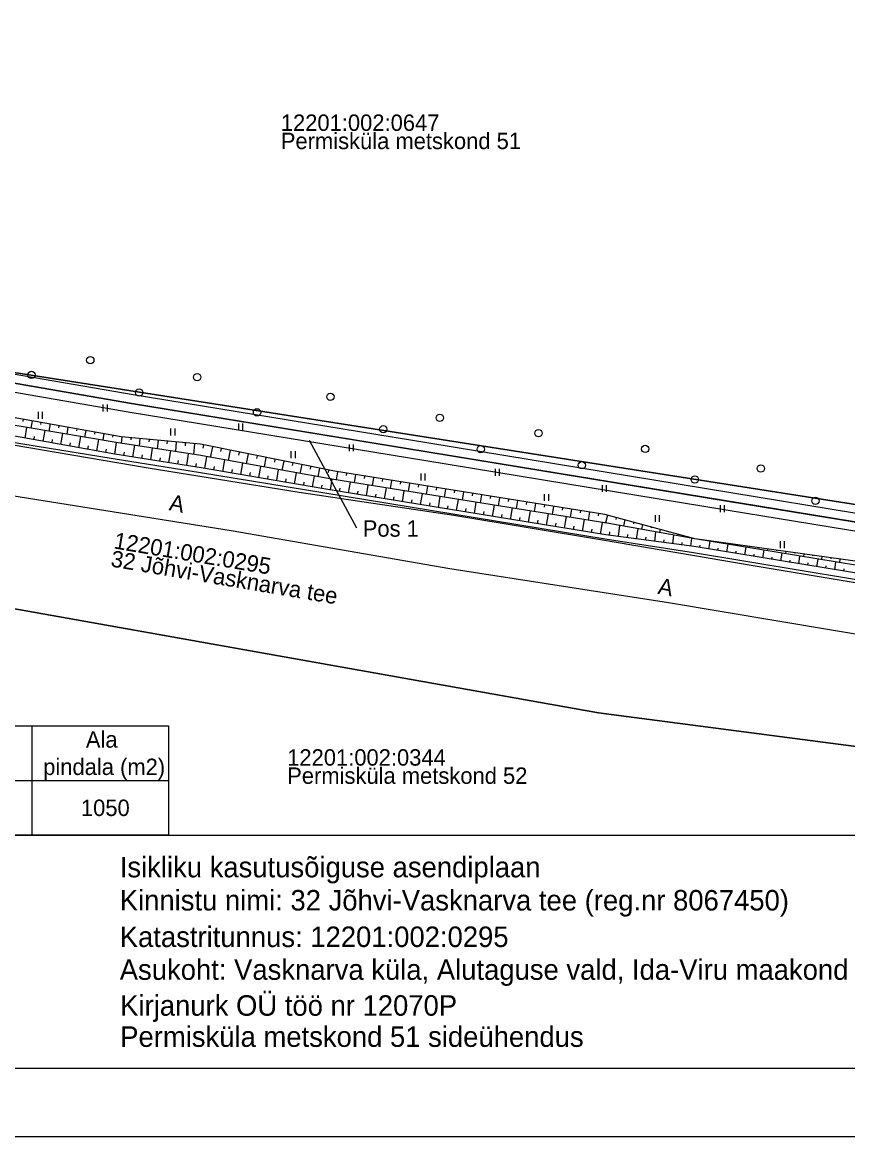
# Model space of a CAD drawing. Extents: x 712851 to 713448, y 6545714 to 6545930.
# Drawn here: x 713128.6 to 713219.1, y 6545742.3 to 6545864.7 of the extents above; entities that cross this region are included whole.
import ezdxf

# ---------------------------------------------------------------- set-up
doc = ezdxf.new("R2010")
doc.units = 0
for name, color, linetype in [('HALJASTUS', 7, 'Continuous'), ('KASUTUSALA', 7, 'Continuous'), ('PIIR', 7, 'Continuous'), ('PR_SIDE', 7, 'Continuous'), ('RELJEEF', 7, 'Continuous'), ('SITRASS', 7, 'Continuous'), ('TEE', 7, 'Continuous'), ('VORMISTUS_1', 7, 'Continuous')]:
    doc.layers.add(name, color=color, linetype=linetype)

msp = doc.modelspace()

# ---------------------------------------------------------------- linework, layer by layer
at = {"layer": 'HALJASTUS'}
for p, q in [((713130.29, 6545821.9), (713130.29, 6545821.14)), ((713130.74, 6545821.9), (713130.74, 6545821.14)), ((713137.41, 6545822.71), (713137.41, 6545821.95)), ((713137.87, 6545822.71), (713137.87, 6545821.95)), ((713152.26, 6545820.64), (713152.26, 6545819.88)), ((713152.71, 6545820.64), (713152.71, 6545819.88)), ((713144.83, 6545820.07), (713144.83, 6545819.31)), ((713145.29, 6545820.07), (713145.29, 6545819.31)), ((713164.41, 6545818.33), (713164.41, 6545817.57)), ((713164.86, 6545818.33), (713164.86, 6545817.57)), ((713158.03, 6545817.59), (713158.03, 6545816.82)), ((713158.49, 6545817.59), (713158.49, 6545816.82)), ((713180.42, 6545815.64), (713180.42, 6545814.88)), ((713180.87, 6545815.64), (713180.87, 6545814.88)), ((713172.28, 6545815.13), (713172.28, 6545814.37)), ((713172.73, 6545815.13), (713172.73, 6545814.37)), ((713192.18, 6545813.87), (713192.18, 6545813.11)), ((713192.63, 6545813.87), (713192.63, 6545813.11)), ((713185.83, 6545812.88), (713185.83, 6545812.12)), ((713186.29, 6545812.88), (713186.29, 6545812.12)), ((713205.11, 6545811.66), (713205.11, 6545810.89)), ((713205.56, 6545811.66), (713205.56, 6545810.89)), ((713197.98, 6545810.58), (713197.98, 6545809.82)), ((713198.44, 6545810.58), (713198.44, 6545809.82)), ((713211.69, 6545807.7), (713211.69, 6545806.94)), ((713212.15, 6545807.7), (713212.15, 6545806.94))]:
    msp.add_line(p, q, dxfattribs=at)
msp.add_lwpolyline([(713243.24, 6545806.02), (713233.71, 6545807.55), (713140.54, 6545822.83), (713103.81, 6545829.17), (713056.1, 6545836.44)], dxfattribs=at)
for centre in [(713136.02, 6545827.57), (713129.56, 6545825.95), (713147.75, 6545825.71), (713141.38, 6545824.03), (713162.36, 6545823.55), (713154.31, 6545821.85), (713174.36, 6545821.25), (713168.16, 6545819.99), (713185.19, 6545819.57), (713178.85, 6545817.8), (713196.9, 6545817.83), (713189.95, 6545816.04), (713209.58, 6545815.68), (713202.34, 6545814.48), (713215.57, 6545812.14)]:
    msp.add_circle(centre, 0.4, dxfattribs=at)
at = {"layer": 'KASUTUSALA'}
for points in [[(713019.19, 6545842.89), (713110.14, 6545828.97), (713117.77, 6545827.77), (713140.71, 6545823.82), (713173.15, 6545818.49), (713206.31, 6545813.05), (713233.87, 6545808.53)], [(713233.55, 6545806.56), (713205.99, 6545811.08), (713172.83, 6545816.52), (713140.38, 6545821.84), (713103.65, 6545828.18), (713077.53, 6545832.15), (713021.99, 6545840.54)]]:
    msp.add_lwpolyline(points, dxfattribs=at)
at = {"layer": 'PIIR'}
for points in [[(713056.1, 6545837.24), (713110.14, 6545828.97), (713225.78, 6545810.83), (713243.24, 6545807.88)], [(713243.24, 6545807.88), (713225.78, 6545810.83), (713110.14, 6545828.97), (713056.1, 6545837.24)], [(713056.1, 6545813.14), (713059.74, 6545812.48), (713083.79, 6545807.67), (713123.38, 6545801.06), (713158.31, 6545794.82), (713191.79, 6545788.86), (713223.65, 6545784.69), (713243.24, 6545781.2)], [(713243.24, 6545781.2), (713223.65, 6545784.69), (713191.79, 6545788.86), (713158.31, 6545794.82), (713123.38, 6545801.06), (713083.79, 6545807.67), (713059.74, 6545812.48), (713056.1, 6545813.14)]]:
    msp.add_lwpolyline(points, dxfattribs=at)
at = {"layer": 'PR_SIDE'}
msp.add_lwpolyline([(713056.1, 6545836.4), (713077.68, 6545833.14), (713103.81, 6545829.17), (713140.54, 6545822.83), (713172.99, 6545817.5), (713206.15, 6545812.06), (713233.71, 6545807.55), (713243.24, 6545806.02)], dxfattribs=at)
at = {"layer": 'RELJEEF'}
for p, q in [((713128.64, 6545821.09), (713128.6, 6545820.85)), ((713129.63, 6545820.92), (713129.49, 6545820.12)), ((713130.61, 6545820.74), (713130.57, 6545820.51)), ((713131.6, 6545820.57), (713131.46, 6545819.79)), ((713128.87, 6545819.03), (713129.07, 6545820.19)), ((713130.83, 6545818.68), (713131.05, 6545819.86)), ((713132.58, 6545820.39), (713132.54, 6545820.16)), ((713132.8, 6545818.32), (713133.02, 6545819.53)), ((713133.57, 6545820.21), (713133.43, 6545819.46)), ((713134.55, 6545820.04), (713134.51, 6545819.81)), ((713135.53, 6545819.86), (713135.4, 6545819.13)), ((713136.52, 6545819.69), (713136.48, 6545819.47)), ((713137.5, 6545819.51), (713137.38, 6545818.79)), ((713138.49, 6545819.33), (713138.45, 6545819.12)), ((713129.85, 6545818.85), (713129.91, 6545819.2)), ((713131.82, 6545818.5), (713131.88, 6545818.86)), ((713133.79, 6545818.15), (713133.85, 6545818.51)), ((713134.77, 6545817.97), (713134.99, 6545819.19)), ((713135.76, 6545817.8), (713135.82, 6545818.17)), ((713136.74, 6545817.62), (713136.96, 6545818.86)), ((713138.71, 6545817.27), (713138.91, 6545818.54)), ((713139.47, 6545819.16), (713139.41, 6545818.46)), ((713140.47, 6545819.07), (713140.45, 6545818.84)), ((713140.68, 6545816.96), (713140.89, 6545818.23)), ((713141.46, 6545818.97), (713141.39, 6545818.15)), ((713142.46, 6545818.88), (713142.43, 6545818.62)), ((713143.45, 6545818.79), (713143.37, 6545817.84)), ((713144.45, 6545818.69), (713144.42, 6545818.39)), ((713145.45, 6545818.6), (713145.35, 6545817.54)), ((713146.44, 6545818.5), (713146.41, 6545818.17)), ((713147.44, 6545818.41), (713147.33, 6545817.23)), ((713148.43, 6545818.28), (713148.36, 6545817.92)), ((713149.41, 6545818.08), (713149.17, 6545816.91)), ((713137.72, 6545817.44), (713137.79, 6545817.82)), ((713139.7, 6545817.11), (713139.76, 6545817.49)), ((713141.67, 6545816.8), (713141.73, 6545817.18)), ((713142.66, 6545816.64), (713142.86, 6545817.92)), ((713143.65, 6545816.49), (713143.71, 6545816.87)), ((713144.64, 6545816.33), (713144.84, 6545817.62)), ((713146.61, 6545816.02), (713146.81, 6545817.31)), ((713148.59, 6545815.71), (713148.81, 6545816.98)), ((713150.39, 6545817.89), (713150.32, 6545817.54)), ((713151.37, 6545817.69), (713151.14, 6545816.56)), ((713152.35, 6545817.49), (713152.28, 6545817.16)), ((713153.33, 6545817.29), (713153.11, 6545816.2)), ((713154.31, 6545817.09), (713154.24, 6545816.77)), ((713155.29, 6545816.9), (713155.08, 6545815.85)), ((713145.62, 6545816.18), (713145.68, 6545816.56)), ((713147.6, 6545815.87), (713147.66, 6545816.25)), ((713149.57, 6545815.54), (713149.64, 6545815.92)), ((713150.56, 6545815.37), (713150.77, 6545816.62)), ((713152.53, 6545815.03), (713152.74, 6545816.27)), ((713154.5, 6545814.69), (713154.71, 6545815.91)), ((713156.27, 6545816.7), (713156.21, 6545816.39)), ((713157.25, 6545816.5), (713157.05, 6545815.49)), ((713158.23, 6545816.3), (713158.17, 6545816.01)), ((713159.21, 6545816.11), (713159.02, 6545815.14)), ((713160.19, 6545815.91), (713160.13, 6545815.62)), ((713161.17, 6545815.71), (713160.98, 6545814.78)), ((713151.54, 6545815.2), (713151.61, 6545815.57)), ((713153.51, 6545814.86), (713153.58, 6545815.23)), ((713155.48, 6545814.52), (713155.55, 6545814.88)), ((713156.47, 6545814.35), (713156.68, 6545815.56)), ((713157.46, 6545814.18), (713157.52, 6545814.54)), ((713158.44, 6545814.01), (713158.65, 6545815.2)), ((713160.41, 6545813.67), (713160.62, 6545814.85)), ((713162.15, 6545815.51), (713162.1, 6545815.24)), ((713162.38, 6545813.34), (713162.57, 6545814.5)), ((713163.13, 6545815.33), (713162.99, 6545814.43)), ((713164.12, 6545815.17), (713164.08, 6545814.9)), ((713165.11, 6545815.01), (713164.97, 6545814.11)), ((713166.1, 6545814.85), (713166.05, 6545814.59)), ((713167.08, 6545814.7), (713166.94, 6545813.8)), ((713168.07, 6545814.54), (713168.03, 6545814.27)), ((713159.43, 6545813.84), (713159.49, 6545814.19)), ((713161.4, 6545813.5), (713161.46, 6545813.85)), ((713163.37, 6545813.17), (713163.43, 6545813.52)), ((713164.36, 6545813.01), (713164.55, 6545814.18)), ((713165.35, 6545812.85), (713165.4, 6545813.2)), ((713166.33, 6545812.69), (713166.52, 6545813.87)), ((713168.31, 6545812.37), (713168.5, 6545813.55)), ((713169.06, 6545814.38), (713168.92, 6545813.48)), ((713170.05, 6545814.22), (713170, 6545813.95)), ((713170.28, 6545812.04), (713170.47, 6545813.24)), ((713171.03, 6545814.06), (713170.89, 6545813.17)), ((713172.02, 6545813.91), (713171.98, 6545813.64)), ((713173.01, 6545813.75), (713172.87, 6545812.85)), ((713174, 6545813.59), (713173.95, 6545813.32)), ((713174.98, 6545813.43), (713174.84, 6545812.54)), ((713175.97, 6545813.27), (713175.93, 6545813.01)), ((713167.32, 6545812.53), (713167.38, 6545812.88)), ((713169.29, 6545812.2), (713169.35, 6545812.56)), ((713171.27, 6545811.88), (713171.32, 6545812.24)), ((713172.25, 6545811.72), (713172.45, 6545812.92)), ((713174.23, 6545811.4), (713174.42, 6545812.61)), ((713176.2, 6545811.07), (713176.4, 6545812.29)), ((713176.96, 6545813.12), (713176.82, 6545812.22)), ((713177.95, 6545812.96), (713177.9, 6545812.69)), ((713178.17, 6545810.75), (713178.37, 6545811.98)), ((713178.93, 6545812.8), (713178.79, 6545811.91)), ((713179.92, 6545812.64), (713179.88, 6545812.38)), ((713180.91, 6545812.48), (713180.77, 6545811.59)), ((713181.9, 6545812.33), (713181.85, 6545812.06)), ((713182.88, 6545812.17), (713182.74, 6545811.28)), ((713183.87, 6545812.01), (713183.83, 6545811.74)), ((713173.24, 6545811.56), (713173.3, 6545811.92)), ((713175.21, 6545811.24), (713175.27, 6545811.6)), ((713177.19, 6545810.91), (713177.25, 6545811.28)), ((713179.16, 6545810.59), (713179.22, 6545810.96)), ((713180.15, 6545810.43), (713180.35, 6545811.66)), ((713182.12, 6545810.1), (713182.33, 6545811.35)), ((713184.1, 6545809.78), (713184.3, 6545811.03)), ((713184.86, 6545811.85), (713184.72, 6545810.97)), ((713185.85, 6545811.69), (713185.8, 6545811.43)), ((713186.83, 6545811.54), (713186.69, 6545810.65)), ((713187.82, 6545811.38), (713187.78, 6545811.11)), ((713188.81, 6545811.22), (713188.67, 6545810.34)), ((713189.79, 6545811.06), (713189.75, 6545810.8)), ((713190.78, 6545810.9), (713190.64, 6545810.02)), ((713191.77, 6545810.75), (713191.73, 6545810.48)), ((713181.13, 6545810.27), (713181.2, 6545810.64)), ((713183.11, 6545809.94), (713183.17, 6545810.32)), ((713185.08, 6545809.62), (713185.14, 6545810)), ((713186.07, 6545809.46), (713186.28, 6545810.72)), ((713187.06, 6545809.3), (713187.12, 6545809.68)), ((713188.04, 6545809.13), (713188.25, 6545810.4)), ((713190.02, 6545808.81), (713190.23, 6545810.09)), ((713191.99, 6545808.49), (713192.2, 6545809.77)), ((713192.75, 6545810.56), (713192.53, 6545809.72)), ((713193.72, 6545810.3), (713193.66, 6545810.07)), ((713194.68, 6545810.04), (713194.5, 6545809.38)), ((713195.65, 6545809.78), (713195.6, 6545809.61)), ((713196.61, 6545809.52), (713196.48, 6545809.02)), ((713189.03, 6545808.97), (713189.09, 6545809.35)), ((713191, 6545808.65), (713191.07, 6545809.03)), ((713192.98, 6545808.34), (713193.03, 6545808.72)), ((713193.97, 6545808.21), (713194.13, 6545809.44)), ((713194.96, 6545808.08), (713195.01, 6545808.43)), ((713195.95, 6545807.94), (713196.11, 6545809.09)), ((713197.58, 6545809.26), (713197.55, 6545809.14)), ((713197.94, 6545807.68), (713198.08, 6545808.74)), ((713198.55, 6545809), (713198.46, 6545808.67)), ((713199.51, 6545808.74), (713199.49, 6545808.67)), ((713199.92, 6545807.42), (713200.05, 6545808.39)), ((713200.48, 6545808.48), (713200.43, 6545808.32)), ((713196.94, 6545807.81), (713196.99, 6545808.14)), ((713198.93, 6545807.55), (713198.97, 6545807.85)), ((713200.91, 6545807.28), (713200.95, 6545807.56)), ((713201.44, 6545808.23), (713201.44, 6545808.2)), ((713201.9, 6545807.15), (713202.02, 6545808.04)), ((713202.41, 6545807.97), (713202.41, 6545807.97)), ((713202.89, 6545807), (713202.93, 6545807.26)), ((713203.4, 6545807.83), (713203.4, 6545807.83)), ((713203.88, 6545806.84), (713204.02, 6545807.71)), ((713204.39, 6545807.69), (713204.38, 6545807.64)), ((713205.38, 6545807.56), (713205.38, 6545807.53)), ((713205.85, 6545806.52), (713205.99, 6545807.38)), ((713206.37, 6545807.42), (713206.36, 6545807.32)), ((713207.36, 6545807.28), (713207.36, 6545807.24)), ((713207.82, 6545806.19), (713207.96, 6545807.05)), ((713208.35, 6545807.14), (713208.33, 6545806.99)), ((713204.86, 6545806.68), (713204.91, 6545806.94)), ((713206.84, 6545806.35), (713206.88, 6545806.61)), ((713208.81, 6545806.03), (713208.85, 6545806.29)), ((713209.34, 6545807), (713209.34, 6545806.95)), ((713209.8, 6545805.87), (713209.94, 6545806.73)), ((713210.33, 6545806.86), (713210.31, 6545806.67)), ((713210.78, 6545805.71), (713210.83, 6545805.96)), ((713211.32, 6545806.72), (713211.31, 6545806.66)), ((713211.77, 6545805.55), (713211.91, 6545806.4)), ((713212.31, 6545806.58), (713212.28, 6545806.34)), ((713213.3, 6545806.45), (713213.29, 6545806.37)), ((713213.74, 6545805.22), (713213.88, 6545806.08)), ((713214.29, 6545806.31), (713214.25, 6545806.01)), ((713215.28, 6545806.17), (713215.27, 6545806.07)), ((713216.27, 6545806.03), (713216.23, 6545805.69)), ((713217.27, 6545805.89), (713217.25, 6545805.78)), ((713212.76, 6545805.38), (713212.8, 6545805.64)), ((713214.73, 6545805.06), (713214.77, 6545805.32)), ((713215.72, 6545804.9), (713215.86, 6545805.75)), ((713216.7, 6545804.74), (713216.75, 6545804.99)), ((713217.69, 6545804.57), (713217.83, 6545805.42)), ((713218.26, 6545805.75), (713218.2, 6545805.36)), ((713218.68, 6545804.41), (713218.72, 6545804.67))]:
    msp.add_line(p, q, dxfattribs=at)
for points in [[(713243.24, 6545801.22), (713231.35, 6545803.19), (713202.36, 6545807.98), (713192.9, 6545809.66), (713162.51, 6545814.51), (713147.93, 6545817.14), (713139.09, 6545818.51), (713101.26, 6545824.85), (713071.24, 6545829.69), (713056.1, 6545832.11)], [(713243.24, 6545800.24), (713231.01, 6545802.39), (713202.26, 6545807.11), (713192.59, 6545808.39), (713161.64, 6545813.46), (713148.19, 6545815.77), (713138.71, 6545817.27), (713101, 6545824.02), (713071.19, 6545828.4), (713056.1, 6545830.91)], [(713243.24, 6545801.93), (713231.49, 6545803.9), (713202.36, 6545807.98), (713192.46, 6545810.64), (713162.81, 6545815.38), (713148.11, 6545818.35), (713139.41, 6545819.17), (713101.58, 6545825.94), (713071.27, 6545830.36), (713066.71, 6545830.83), (713065.42, 6545830.62)]]:
    msp.add_lwpolyline(points, dxfattribs=at)
at = {"layer": 'SITRASS'}
msp.add_lwpolyline([(713056.1, 6545829.95), (713058.57, 6545829.54), (713075.45, 6545826.79), (713092.23, 6545824.13), (713109.17, 6545821.25), (713125.8, 6545818.59), (713142.35, 6545815.77), (713158.95, 6545813.1), (713175.9, 6545810.55), (713192.21, 6545807.84), (713208.75, 6545805.03), (713225.63, 6545802.21), (713242.15, 6545799.55), (713243.24, 6545799.36)], dxfattribs=at)
at = {"layer": 'TEE'}
for points in [[(713243.24, 6545799.61), (713230.89, 6545801.68), (713202.19, 6545806.43), (713192.51, 6545807.93), (713161.54, 6545813.03), (713148.12, 6545815.2), (713138.51, 6545816.74), (713099.99, 6545823), (713071.09, 6545827.96), (713056.1, 6545830.32)], [(713056.1, 6545824.37), (713078.1, 6545820.77), (713102.91, 6545816.61), (713127.41, 6545812.72), (713151.46, 6545808.88), (713175.45, 6545804.71), (713199.46, 6545800.99), (713223.02, 6545797.04), (713243.24, 6545793.65)]]:
    msp.add_lwpolyline(points, dxfattribs=at)
at = {"layer": 'VORMISTUS_1'}
for p, q in [((713160.03, 6545818.81), (713165.21, 6545809.16)), ((713129.6, 6545787.44), (713129.6, 6545775.44)), ((713056.1, 6545781.44), (713144.6, 6545781.44))]:
    msp.add_line(p, q, dxfattribs=at)
for points in [[(713038.1, 6545899.84), (713260.85, 6545899.84), (713260.85, 6545742.34), (713038.1, 6545742.34)], [(713046.35, 6545749.84), (713046.35, 6545892.34), (713252.6, 6545892.34), (713252.6, 6545749.84)], [(713046.35, 6545892.34), (713252.6, 6545892.34), (713252.6, 6545749.84), (713046.35, 6545749.84)], [(713243.24, 6545775.44), (713243.24, 6545885.69), (713056.1, 6545885.69), (713056.1, 6545775.44)], [(713056.1, 6545787.44), (713144.6, 6545787.44), (713144.6, 6545775.44), (713056.1, 6545775.44)]]:
    msp.add_lwpolyline(points, close=True, dxfattribs=at)
msp.add_lwpolyline([(713056.1, 6545775.44), (713243.24, 6545775.44)], dxfattribs=at)

# ---------------------------------------------------------------- texts
at = {"layer": 'PIIR'}
for s, p in [('12201:002:0647', (713156.92, 6545852.74)), ('Permisküla metskond 51', (713156.92, 6545850.74)), ('12201:002:0344', (713157.62, 6545783.07)), ('Permisküla metskond 52', (713157.62, 6545781.07))]:
    msp.add_text(s, height=1.8, dxfattribs=at).set_placement(p)
for s, p in [('12201:002:0295', (713138.51, 6545806.92)), ('32 Jõhvi-Vasknarva tee', (713138.18, 6545804.94))]:
    msp.add_text(s, height=1.8, rotation=350.4647, dxfattribs=at).set_placement(p)
at = {"layer": 'TEE'}
for p in [(713144.58, 6545811.12), (713198.2, 6545801.95)]:
    msp.add_text('A', height=1.8, rotation=348.682, dxfattribs=at).set_placement(p)
at = {"layer": 'VORMISTUS_1'}
for s, height, p in [('Pos 1', 1.8, (713165.91, 6545808.2)), ('Ala', 1.8, (713135.53, 6545785.04)), ('pindala (m2)', 1.8, (713130.85, 6545782.04)), ('1050', 1.8, (713134.99, 6545777.54)), ('Isikliku kasutusõiguse asendiplaan', 2.25, (713139.25, 6545770.81)), ('Kinnistu nimi: 32 Jõhvi-Vasknarva tee (reg.nr 8067450)', 2.25, (713139.25, 6545767.17)), ('Katastritunnus: 12201:002:0295', 2.25, (713139.25, 6545763.16)), ('Asukoht: Vasknarva küla, Alutaguse vald, Ida-Viru maakond', 2.25, (713139.25, 6545759.56))]:
    msp.add_text(s, height=height, dxfattribs=at).set_placement(p)
for s, p in [('Kirjanurk OÜ töö nr 12070P', (713139.3, 6545755.62)), ('Permisküla metskond 51 sideühendus', (713139.3, 6545752.2))]:
    msp.add_text(s, height=2.25, rotation=360, dxfattribs=at).set_placement(p)

doc.saveas('drawing.dxf')
